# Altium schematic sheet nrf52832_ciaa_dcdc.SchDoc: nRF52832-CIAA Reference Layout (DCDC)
size A4; Revision: 1.0; SheetNumber: 1; SheetTotal: 1; DrawnBy: RUBR; DocumentSize: A4; PCAName: nRF52832-CIAA Reference Layout (DCDC)
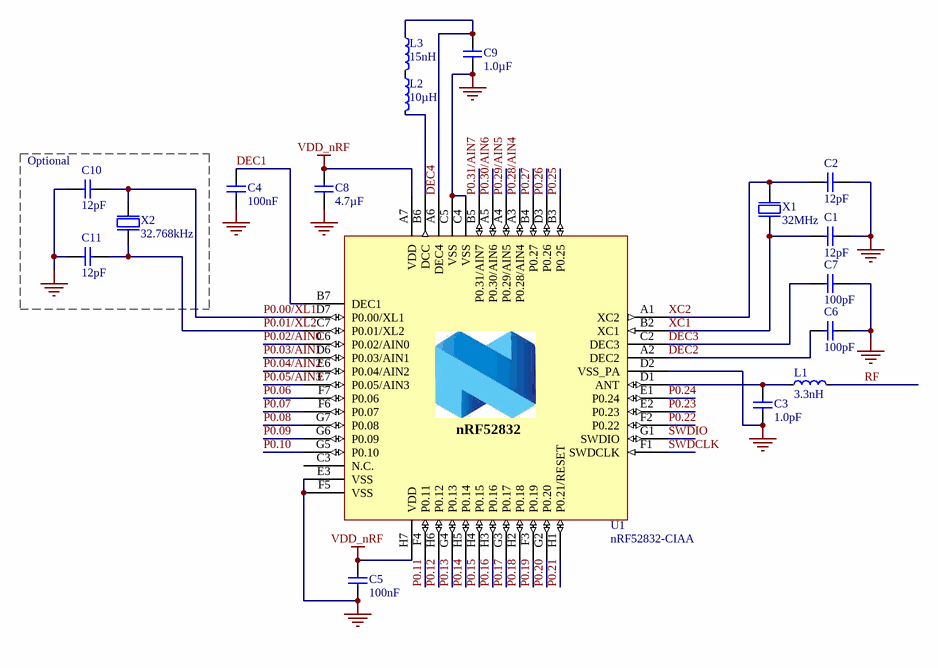
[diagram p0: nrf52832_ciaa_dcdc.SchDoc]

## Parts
C1  12pF  [CAPC0603X03L]
C2  12pF  [CAPC0603X03L]
C3  1.0pF  [CAPC0603X03L]
C4  100nF  [CAPC0603X03L]
C5  100nF  [CAPC0603X03L]
C6  100pF  [CAPC0603X03L]
C7  100pF  [CAPC0603X03L]
C8  4.7µF  [CAPC1608X06L]
C9  1.0µF  [CAPC1005X04L]
C10  12pF  [CAPC0603X03L]
C11  12pF  [CAPC0603X03L]
L1  3.3nH  [INDC0603X03L]
L2  10µH  [INDC1608X06L]
L3  15nH  [INDC1005X04L]
U1  nRF52832-CIAA  [BGA50C40P7X8_295X322X50]
X1  32MHz  [BT-XTAL_2016]
X2  32.768kHz  [XTAL_2012]

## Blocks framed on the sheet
Optional: C10 C11 X2

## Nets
GND: C1.1 C2.1 C3.1 C4.2 C5.2 C6.1 C7.2 C8.2 C9.1 C10.1 C11.1 U1.C4(VSS) U1.C5(VSS) U1.D2(VSS_PA) U1.E3(VSS) U1.F5(VSS) X1.2(GND) X1.4(GND)
VDD_nRF: C5.1 C8.1 U1.A7(VDD) U1.H7(VDD)
DEC1: C4.1 U1.B7(DEC1)
DEC2: C6.2 U1.A2(DEC2)
DEC3: C7.1 U1.C2(DEC3)
DEC4: C9.2 L3.1 U1.A6(DEC4)
P0.00/XL1: C10.2 U1.D7(P0.00/XL1) X2.1(inp)
P0.01/XL2: C11.2 U1.C7(P0.01/XL2) X2.2(out)
P0.02/AIN0: U1.C6(P0.02/AIN0)
P0.03/AIN1: U1.D6(P0.03/AIN1)
P0.04/AIN2: U1.E6(P0.04/AIN2)
P0.05/AIN3: U1.E7(P0.05/AIN3)
P0.06: U1.F7(P0.06)
P0.07: U1.F6(P0.07)
P0.08: U1.G7(P0.08)
P0.09: U1.G6(P0.09)
P0.10: U1.G5(P0.10)
P0.11: U1.F4(P0.11)
P0.12: U1.H6(P0.12)
P0.13: U1.G4(P0.13)
P0.14: U1.H5(P0.14)
P0.15: U1.H4(P0.15)
P0.16: U1.H3(P0.16)
P0.17: U1.G3(P0.17)
P0.18: U1.H2(P0.18)
P0.19: U1.F3(P0.19)
P0.20: U1.G2(P0.20)
P0.21: U1.H1(P0.21/RESET)
P0.22: U1.F2(P0.22)
P0.23: U1.E2(P0.23)
P0.24: U1.E1(P0.24)
P0.25: U1.B3(P0.25)
P0.26: U1.D3(P0.26)
P0.27: U1.B4(P0.27)
P0.28/AIN4: U1.A3(P0.28/AIN4)
P0.29/AIN5: U1.A4(P0.29/AIN5)
P0.30/AIN6: U1.A5(P0.30/AIN6)
P0.31/AIN7: U1.B5(P0.31/AIN7)
RF: L1.2
SWDCLK: U1.F1(SWDCLK)
SWDIO: U1.G1(SWDIO)
XC1: C1.2 U1.B2(XC1) X1.1(inp)
XC2: C2.2 U1.A1(XC2) X1.3(out)
NetC3_2: C3.2 L1.1 U1.D1(ANT)
NetL2_1: L2.1 L3.2
NetL2_2: L2.2 U1.B6(DCC)

Not connected (* = marked no-connect by the designer): U1 C3(N.C.)

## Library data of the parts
C1 C2 C10 C11 = C0201-12p: Capacitor, NP0, ±2%; Note: 50V; Artikkelnr Noca: N.A.
C3 = C0201-1.0p: Capacitor, NP0, ±5%; Note: Chip Cap 1%; Artikkelnr Noca: N.A.
C4 C5 = C0201-100n: Capacitor, X7R, ±10%; Note: 16V; Artikkelnr Noca: N.A.
C6 C7 = C0201-100p: Capacitor, NP0, ±5%; Note: Chip Cap 1%; Artikkelnr Noca: N.A.
C8 = C0603-4µ7: Capacitor, X5R, ±10%; Note: 6.3V; Artikkelnr Noca: 20069060; Artikkelnr Simpro: N.A.
C9 = C0402-1µ0: Capacitor, X5R, ±5%; Note: 6.3V; Artikkelnr Noca: 20039235; Artikkelnr Simpro: N.A.
L1 = L0201-3n3: High frequency chip inductor ±5%; Artikkelnr Noca: N.A.
L2 = L0603-10µ: Chip inductor, IDC,min = 50 mA, ±20%; Manufacturer: Taiyo Yuden; Manufacturer Part Number: LBMF1608T100K; 2nd source part number: 178-6105; Note: LBMF1608T100K 10µH 80mA 0603; Artikkelnr Noca: 33029314; Artikkelnr Simpro: N.A.
L3 = L0402-15n: High frequency chip inductor ±10%; Manufacturer: Taiyo Yuden; Manufacturer Part Number: HK100515NJ-T; 2nd source part number: 658-1328; Artikkelnr Noca: 33029323; Artikkelnr Simpro: N.A.
U1 = nRF52832-CIAA: Multi-protocol Bluetooth Low Energy, ANT and 2.4GHz proprietary system-on-chip; Manufacturer: Nordic Semiconductor; Artikkelnr Noca: N.A.
X1 = XTAL_SMD2016_32MHz_8pF_Epson: XTAL SMD 2016, 32MHz, Cl=8pF, Total Tol: ±40ppm; Manufacturer: Epson Toyocom; Manufacturer Part Number: Q22FA12800025; Note: XTAL SMD 32.000MHz; Artikkelnr Noca: N.A.
X2 = XTAL_SMD2012_32.768kHz_9pF_Seiko: XTAL SMD 2012, 32.768kHz, Cl=9pF, Total Tol: ±50ppm; Manufacturer: Seiko; Manufacturer Part Number: SC20S-9.0PF20PPM; Note: XTAL SMD 32.768kHz, 2012; Artikkelnr Noca: N.A.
